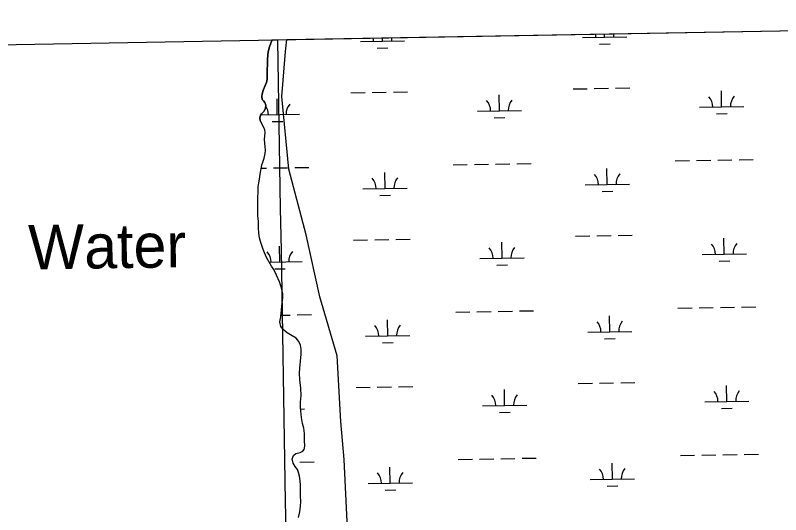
# Model space of a CAD drawing. Extents: x 3903937 to 3942190, y 260677 to 286651.
# Drawn here: x 3912613 to 3914342, y 283217 to 284345 of the extents above; entities that cross this region are included whole.
import ezdxf

# ---------------------------------------------------------------- set-up
doc = ezdxf.new("R2010")
doc.units = 0
for name, color, linetype in [('V-GRID-FRAM', 7, 'Continuous'), ('V-GRID-MAJR', 7, 'Continuous'), ('V-RIVR-IDEN', 7, 'Continuous'), ('V-SITE-VEGE', 7, 'Continuous'), ('V-TOPO-SHOR', 7, 'Continuous'), ('V-WETL-SWMP', 7, 'Continuous')]:
    doc.layers.add(name, color=color, linetype=linetype)

msp = doc.modelspace()

# ---------------------------------------------------------------- linework, layer by layer
at = {"layer": 'V-GRID-FRAM'}
msp.add_lwpolyline([(3907892.224, 284196.099), (3939773.201, 284757.23600000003), (3940101.116, 266577.619), (3908204.273, 266016.203), (3907892.224, 284196.099)], dxfattribs=at)
at = {"layer": 'V-GRID-MAJR'}
msp.add_spline([(3913520.414, 266109.772), (3913415.549, 272167.798), (3913310.651, 278227.748), (3913205.754, 284287.69), (3913205.721, 284289.62200000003)], degree=3, dxfattribs=at)
at = {"layer": 'V-SITE-VEGE'}
for p, q in [((3913226.6025512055, 284289.98938413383), (3914840.3981272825, 284318.39379621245)), ((3913223.1040000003, 284263.156), (3913226.6025512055, 284289.98938413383)), ((3913215.301, 284161.6679999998), (3913223.1040000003, 284263.156)), ((3913230.907, 283997.723), (3913215.301, 284161.6679999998)), ((3913269.921, 283849.395), (3913230.907, 283997.723)), ((3913301.137, 283708.869), (3913269.921, 283849.395)), ((3913340.149, 283576.153), (3913301.137, 283708.869)), ((3913347.952, 283427.822), (3913340.149, 283576.153)), ((3913355.755, 283341.946), (3913347.952, 283427.822)), ((3913363.558, 283185.808), (3913355.755, 283341.946))]:
    msp.add_line(p, q, dxfattribs=at)
at = {"layer": 'V-TOPO-SHOR'}
for points in [[(3913193.2026698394, 284289.40151290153), (3913190.299, 284282.066), (3913187.352, 284273.605), (3913184.211, 284262.196), (3913183.23, 284255.9), (3913182.646, 284244.294), (3913182.847, 284232.099), (3913182.0640000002, 284223.048), (3913181.872, 284213.214), (3913181.878, 284200.428), (3913180.504, 284193.344), (3913176.967, 284186.262), (3913173.626, 284177.016), (3913170.2860000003, 284167.572), (3913169.698, 284161.473), (3913170.882, 284154.787), (3913173.637, 284151.837), (3913176.393, 284147.903), (3913178.558, 284141.61), (3913178.169, 284135.316), (3913175.222, 284128.431), (3913169.322, 284122.721), (3913166.569, 284119.18), (3913165.59, 284112.295), (3913166.379, 284107.574), (3913173.151, 284093.666)], [(3913192.001, 283778.561), (3913180.559, 283798.355), (3913175.81, 283808.81200000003), (3913172.037, 283818.02400000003), (3913169.463, 283825.14), (3913166.5360000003, 283834.26), (3913164.591, 283842.29), (3913163.075, 283853.155), (3913162.426, 283865.162), (3913161.893, 283879.628), (3913160.9450000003, 283892.253), (3913160.558, 283906.254), (3913161.119, 283921.777), (3913161.779, 283957.443), (3913163.163, 283966.881), (3913164.376, 283975.24), (3913165.858, 283985.982), (3913167.231, 283994.647), (3913168.734, 284002.006), (3913170.128, 284007.365), (3913171.691, 284013.569), (3913174.833, 284022.36100000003), (3913177.538, 284032.619), (3913178.275, 284040.14400000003), (3913177.555, 284047.69), (3913176.3030000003, 284055.938), (3913175.824, 284064.173), (3913176.572, 284072.389), (3913177.3740000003, 284079.142), (3913176.275, 284087.158), (3913173.151, 284093.666)], [(3913252.794, 283211.25), (3913255.301, 283223.436), (3913257.203, 283236.4), (3913257.615, 283247.465), (3913257.2630000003, 283258.93), (3913256.7860000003, 283267.39400000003), (3913257.291, 283284.227), (3913256.0670000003, 283293.934), (3913254.623, 283304.492), (3913252.9820000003, 283312.362), (3913250.4020000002, 283319.094), (3913245.134, 283326.176), (3913240.336, 283333.715), (3913238.2630000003, 283343.36100000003), (3913241.004, 283351.004), (3913246.539, 283355.68200000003), (3913256.417, 283357.828), (3913262.383, 283360.652), (3913265.596, 283364.367), (3913266.72, 283371.961), (3913266.3910000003, 283384.806), (3913265.9590000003, 283400.731), (3913264.468, 283412.983), (3913261.637, 283423.331), (3913259.552, 283436.97500000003), (3913257.2260000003, 283459.31200000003), (3913257.1950000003, 283471.539), (3913258.436, 283486.358), (3913257.629, 283502.904), (3913255.407, 283522.163), (3913254.873, 283536.551), (3913255.9050000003, 283547.993), (3913257.16, 283563.658), (3913258.426, 283579.938), (3913258.5300000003, 283591.087), (3913257.363, 283599.717), (3913253.742, 283608.696), (3913247.2460000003, 283615.722), (3913238.265, 283621.481), (3913226.913, 283627.896), (3913217.656, 283635.506), (3913212.61, 283641.969), (3913210.7830000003, 283652.533), (3913212.8170000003, 283664.188), (3913215.944, 283695.50800000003), (3913217.269, 283706.098), (3913217.433, 283716.168), (3913214.4250000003, 283729.675), (3913209.413, 283742.983), (3913202.589, 283758.318), (3913196.72, 283770.871), (3913192.001, 283778.561)]]:
    msp.add_lwpolyline(points, dxfattribs=at)
at = {"layer": 'V-WETL-SWMP'}
for p, q in [((3913193.203086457, 284289.4015202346), (3915021.5893509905, 284321.58294250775)), ((3913190.3000000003, 284282.065), (3913193.203086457, 284289.4015202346)), ((3913392.329723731, 284285.62953828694), (3913492.3142362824, 284287.3894388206)), ((3913442.3219800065, 284286.50948855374), (3913442.1939358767, 284293.78400758)), ((3913894.159990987, 284294.4626198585), (3913994.144503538, 284296.2225203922)), ((3913944.152247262, 284295.34257012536), (3913944.024209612, 284302.61672102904)), ((3913184.21, 284262.195), (3913187.353, 284273.605)), ((3913187.353, 284273.605), (3913190.3000000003, 284282.065)), ((3913430.5954087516, 284270.86969035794), (3913454.591691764, 284271.2920664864)), ((3913932.4256760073, 284279.7027719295), (3913956.4219590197, 284280.12514805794)), ((3913182.645, 284244.294), (3913183.23, 284255.9)), ((3913183.23, 284255.9), (3913184.21, 284262.195)), ((3913182.847, 284232.09799999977), (3913182.645, 284244.294)), ((3913181.872, 284213.21399999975), (3913182.0640000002, 284223.049)), ((3913182.0640000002, 284223.049), (3913182.847, 284232.09799999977)), ((3913181.877, 284200.4279999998), (3913181.872, 284213.21399999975)), ((3913173.626, 284177.016), (3913176.966, 284186.262)), ((3913176.966, 284186.262), (3913180.503, 284193.34499999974)), ((3913180.503, 284193.34499999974), (3913181.877, 284200.4279999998)), ((3913169.699, 284161.474), (3913170.2860000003, 284167.572)), ((3913170.2860000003, 284167.572), (3913173.626, 284177.016)), ((3913370.956837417, 284169.8034582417), (3913402.9518814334, 284170.3666264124)), ((3913418.9494034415, 284170.6482104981), (3913450.9444474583, 284171.2113786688)), ((3913466.9419694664, 284171.4929627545), (3913498.9370134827, 284172.05613092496)), ((3913872.787104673, 284178.6365398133), (3913904.7821486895, 284179.199707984)), ((3913920.779670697, 284179.48129206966), (3913952.774714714, 284180.04446024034)), ((3913968.772236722, 284180.32604432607), (3914000.7672807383, 284180.8892124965)), ((3914208.396367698, 284138.1066519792), (3914207.762803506, 284174.1010764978)), ((3913170.882, 284154.786), (3913169.699, 284161.474)), ((3913173.637, 284151.837), (3913170.882, 284154.786)), ((3913176.393, 284147.904), (3913173.637, 284151.837)), ((3913204.735833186, 284120.4404888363), (3913204.1022689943, 284156.43491335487)), ((3913706.566100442, 284129.2735704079), (3913705.93253625, 284165.2679949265)), ((3913175.221, 284128.42999999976), (3913178.169, 284135.316)), ((3913178.559, 284141.61), (3913176.393, 284147.904)), ((3913178.169, 284135.316), (3913178.559, 284141.61)), ((3914158.4041114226, 284137.2267017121), (3914258.388623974, 284138.98660224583)), ((3913165.59, 284112.295), (3913166.5700000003, 284119.18)), ((3913166.5700000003, 284119.18), (3913169.322, 284122.722)), ((3913167.0337428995, 284119.7768667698), (3913254.7280894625, 284121.3204391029)), ((3913169.322, 284122.722), (3913175.221, 284128.42999999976)), ((3913656.573844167, 284128.3936201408), (3913756.558356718, 284130.15352067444)), ((3914196.669796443, 284122.46685378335), (3914220.6660794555, 284122.88922991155)), ((3913166.378, 284107.575), (3913165.59, 284112.295)), ((3913173.1520000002, 284093.6669999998), (3913166.378, 284107.575)), ((3913193.0092619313, 284104.80069064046), (3913217.0055449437, 284105.22306676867)), ((3913694.8395291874, 284113.633772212), (3913718.8358122, 284114.0561483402)), ((3913176.275, 284087.1569999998), (3913173.1520000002, 284093.6669999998)), ((3913177.375, 284079.14199999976), (3913176.275, 284087.1569999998)), ((3913175.823, 284064.1729999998), (3913176.572, 284072.389)), ((3913176.304, 284055.9379999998), (3913175.823, 284064.1729999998)), ((3913176.572, 284072.389), (3913177.375, 284079.14199999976)), ((3913177.554, 284047.68999999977), (3913176.304, 284055.9379999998)), ((3913178.276, 284040.14299999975), (3913177.554, 284047.68999999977)), ((3913174.833, 284022.35999999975), (3913177.538, 284032.619)), ((3913177.538, 284032.619), (3913178.276, 284040.14299999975)), ((3913170.129, 284007.365), (3913171.691, 284013.568)), ((3913171.691, 284013.568), (3913174.833, 284022.35999999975)), ((3914103.6820452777, 284016.1738997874), (3914135.677089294, 284016.7370679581)), ((3914151.6746113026, 284017.01865204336), (3914183.669655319, 284017.5818202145)), ((3914199.6671773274, 284017.8634042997), (3914231.6622213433, 284018.4265724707)), ((3914247.6597433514, 284018.7081565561), (3914279.6547873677, 284019.2713247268)), ((3913165.859, 283985.982), (3913167.23, 283994.648)), ((3913167.23, 283994.648), (3913168.734, 284002.006)), ((3913168.264471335, 283999.7089309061), (3913180.009120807, 283999.9156570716)), ((3913168.734, 284002.006), (3913170.129, 284007.365)), ((3913196.0066428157, 284000.1972411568), (3913228.0016868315, 284000.76040932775)), ((3913243.99920884, 284001.04199341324), (3913275.9942528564, 284001.6051615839)), ((3913601.851778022, 284007.3408182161), (3913633.8468220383, 284007.9039863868)), ((3913649.844344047, 284008.18557047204), (3913681.839388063, 284008.7487386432)), ((3913697.8369100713, 284009.0303227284), (3913729.831954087, 284009.5934908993)), ((3913745.8294760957, 284009.8750749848), (3913777.824520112, 284010.4382431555)), ((3913950.0069963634, 283962.7190929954), (3913949.373432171, 283998.71351751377)), ((3913164.376, 283975.24099999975), (3913165.859, 283985.982)), ((3913448.1767291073, 283953.88601142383), (3913447.543164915, 283989.8804359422)), ((3913161.779, 283957.4439999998), (3913163.163, 283966.8799999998)), ((3913163.163, 283966.8799999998), (3913164.376, 283975.24099999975)), ((3913900.0147400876, 283961.8391427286), (3913999.999252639, 283963.59904326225)), ((3913161.12, 283921.77699999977), (3913161.779, 283957.4439999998)), ((3913398.184472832, 283953.006061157), (3913498.168985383, 283954.7659616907)), ((3913938.2804251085, 283947.0792947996), (3913962.2767081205, 283947.50167092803)), ((3913436.450157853, 283938.246213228), (3913460.446440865, 283938.6685893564)), ((3913160.559, 283906.254), (3913161.12, 283921.77699999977)), ((3913160.946, 283892.2529999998), (3913160.559, 283906.254)), ((3913161.893, 283879.62699999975), (3913160.946, 283892.2529999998)), ((3913162.426, 283865.1619999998), (3913161.893, 283879.62699999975)), ((3913163.076, 283853.156), (3913162.426, 283865.1619999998)), ((3913164.591, 283842.29), (3913163.076, 283853.156)), ((3913166.5360000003, 283834.261), (3913164.591, 283842.29)), ((3913376.8115865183, 283837.1799811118), (3913408.8066305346, 283837.74314928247)), ((3913424.8041525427, 283838.0247333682), (3913456.799196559, 283838.5879015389)), ((3913472.796718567, 283838.86948562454), (3913504.791762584, 283839.432653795)), ((3913878.641853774, 283846.01306268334), (3913910.6368977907, 283846.576230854)), ((3913926.6344197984, 283846.85781493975), (3913958.6294638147, 283847.42098311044)), ((3913974.626985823, 283847.70256719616), (3914006.6220298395, 283848.2657353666)), ((3914214.251116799, 283805.4831748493), (3914213.617552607, 283841.47759936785)), ((3913169.463, 283825.1399999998), (3913166.5360000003, 283834.261)), ((3913172.038, 283818.02399999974), (3913169.463, 283825.1399999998)), ((3913210.5905822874, 283787.81701170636), (3913209.957018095, 283823.81143622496)), ((3913712.420849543, 283796.6500932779), (3913711.7872853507, 283832.6445177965)), ((3913175.809, 283808.81200000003), (3913172.038, 283818.02399999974)), ((3913180.559, 283798.354), (3913175.809, 283808.81200000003)), ((3914164.2588605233, 283804.6032245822), (3914264.2433730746, 283806.36312511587)), ((3913192.001, 283778.56), (3913180.559, 283798.354)), ((3913186.8910842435, 283787.39985950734), (3913260.5828385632, 283788.696961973)), ((3913662.4285932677, 283795.7701430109), (3913762.413105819, 283797.53004354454)), ((3914202.5245455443, 283789.84337665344), (3914226.5208285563, 283790.26575278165)), ((3913196.72, 283770.86999999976), (3913192.001, 283778.56)), ((3913202.59, 283758.3179999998), (3913196.72, 283770.86999999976)), ((3913198.8640110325, 283772.1772135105), (3913222.8602940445, 283772.5995896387)), ((3913700.6942782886, 283781.0102950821), (3913724.6905613, 283781.4326712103)), ((3913209.414, 283742.982), (3913202.59, 283758.3179999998)), ((3913214.4250000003, 283729.67399999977), (3913209.414, 283742.982)), ((3913217.434, 283716.16899999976), (3913214.4250000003, 283729.67399999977)), ((3913215.944, 283695.509), (3913217.27, 283706.099)), ((3913217.27, 283706.099), (3913217.434, 283716.16899999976)), ((3913212.818, 283664.188), (3913215.944, 283695.509)), ((3914109.5367943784, 283683.5504226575), (3914141.531838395, 283684.1135908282)), ((3914157.5293604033, 283684.3951749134), (3914189.52440442, 283684.95834308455)), ((3914205.5219264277, 283685.2399271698), (3914237.5169704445, 283685.8030953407)), ((3914253.5144924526, 283686.0846794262), (3914285.5095364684, 283686.6478475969)), ((3913213.1757935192, 283667.7729170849), (3913233.8564359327, 283668.13693219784)), ((3913249.8539579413, 283668.4185162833), (3913281.849001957, 283668.98168445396)), ((3913607.7065271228, 283674.7173410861), (3913639.7015711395, 283675.2805092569)), ((3913655.699093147, 283675.5620933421), (3913687.6941371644, 283676.1252615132)), ((3913703.691659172, 283676.4068455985), (3913735.6867031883, 283676.9700137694)), ((3913751.684225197, 283677.25159785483), (3913783.6792692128, 283677.8147660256)), ((3913955.8617454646, 283630.0956158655), (3913955.2281812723, 283666.0900403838)), ((3913210.7830000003, 283652.533), (3913212.818, 283664.188)), ((3913212.61, 283641.969), (3913210.7830000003, 283652.533)), ((3913454.0314782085, 283621.26253429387), (3913453.397914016, 283657.25695881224)), ((3913217.656, 283635.5049999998), (3913212.61, 283641.969)), ((3913226.913, 283627.8949999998), (3913217.656, 283635.5049999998)), ((3913905.869489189, 283629.21566559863), (3914005.85400174, 283630.9755661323)), ((3913238.265, 283621.481), (3913226.913, 283627.8949999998)), ((3913247.245, 283615.722), (3913238.265, 283621.481)), ((3913253.7430000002, 283608.695), (3913247.245, 283615.722)), ((3913404.039221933, 283620.3825840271), (3913504.0237344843, 283622.1424845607)), ((3913944.1351742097, 283614.45581766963), (3913968.1314572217, 283614.87819379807)), ((3913257.364, 283599.7169999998), (3913253.7430000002, 283608.695)), ((3913258.5300000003, 283591.086), (3913257.364, 283599.7169999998)), ((3913442.304906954, 283605.62273609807), (3913466.301189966, 283606.0451122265)), ((3913257.16, 283563.657), (3913258.4250000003, 283579.9379999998)), ((3913258.4250000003, 283579.9379999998), (3913258.5300000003, 283591.086)), ((3913255.9050000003, 283547.992), (3913257.16, 283563.657)), ((3913254.872, 283536.551), (3913255.9050000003, 283547.992)), ((3913255.407, 283522.16399999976), (3913254.872, 283536.551)), ((3913257.63, 283502.904), (3913255.407, 283522.16399999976)), ((3913884.4966028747, 283513.38958555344), (3913916.4916468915, 283513.9527537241)), ((3913932.4891688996, 283514.2343378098), (3913964.484212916, 283514.7975059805)), ((3913980.4817349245, 283515.0790900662), (3914012.4767789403, 283515.64225823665)), ((3913258.436, 283486.35899999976), (3913257.63, 283502.904)), ((3913382.666335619, 283504.5565039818), (3913414.661379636, 283505.1196721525)), ((3913430.658901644, 283505.4012562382), (3913462.65394566, 283505.9644244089)), ((3913478.651467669, 283506.24600849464), (3913510.6465116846, 283506.8091766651)), ((3913718.2755986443, 283464.026616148), (3913717.642034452, 283500.02104066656)), ((3914220.1058659, 283472.85969771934), (3914219.4723017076, 283508.85412223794)), ((3913257.1950000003, 283471.539), (3913258.436, 283486.35899999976)), ((3913257.2260000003, 283459.31199999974), (3913257.1950000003, 283471.539)), ((3913259.5530000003, 283436.97500000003), (3913257.2260000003, 283459.31199999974)), ((3913668.2833423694, 283463.1466658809), (3913768.26785492, 283464.9065664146)), ((3914170.113609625, 283471.97974745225), (3914270.098122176, 283473.73964798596)), ((3914208.3792946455, 283457.2198995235), (3914232.3755776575, 283457.6422756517)), ((3913257.5796213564, 283455.91756929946), (3913266.437587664, 283456.073484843)), ((3913706.5490273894, 283448.38681795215), (3913730.5453104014, 283448.80919408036)), ((3913261.637, 283423.331), (3913259.5530000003, 283436.97500000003)), ((3913264.467, 283412.9819999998), (3913261.637, 283423.331)), ((3913265.9590000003, 283400.7309999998), (3913264.467, 283412.9819999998)), ((3913266.3910000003, 283384.80699999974), (3913265.9590000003, 283400.7309999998)), ((3913265.596, 283364.367), (3913266.72, 283371.961)), ((3913266.72, 283371.961), (3913266.3910000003, 283384.80699999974)), ((3913241.003, 283351.004), (3913246.539, 283355.681)), ((3913246.539, 283355.681), (3913256.416, 283357.827)), ((3913256.416, 283357.827), (3913262.383, 283360.652)), ((3913262.383, 283360.65199999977), (3913265.596, 283364.367)), ((3914259.3692415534, 283353.46120229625), (3914291.36428557, 283354.02437046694)), ((3913238.264, 283343.36), (3913241.003, 283351.004)), ((3913240.336, 283333.714), (3913238.264, 283343.36)), ((3913613.5612762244, 283342.0938639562), (3913645.5563202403, 283342.6570321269)), ((3913661.553842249, 283342.9386162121), (3913693.5488862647, 283343.5017843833)), ((3913709.5464082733, 283343.7833684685), (3913741.5414522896, 283344.34653663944)), ((3913757.5389742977, 283344.6281207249), (3913789.5340183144, 283345.1912888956)), ((3914115.39154348, 283350.92694552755), (3914147.386587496, 283351.49011369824)), ((3914163.384109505, 283351.7716977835), (3914195.379153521, 283352.33486595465)), ((3914211.376675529, 283352.61645003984), (3914243.371719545, 283353.1796182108)), ((3913245.1350000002, 283326.1769999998), (3913240.336, 283333.714)), ((3913250.4020000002, 283319.094), (3913245.1350000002, 283326.1769999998)), ((3913252.983, 283312.3619999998), (3913250.4020000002, 283319.094)), ((3913255.708707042, 283335.79503915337), (3913287.703751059, 283336.35820732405)), ((3913459.8862273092, 283288.63905716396), (3913459.2526631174, 283324.6334816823)), ((3913961.716494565, 283297.4721387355), (3913961.0829303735, 283333.4665632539)), ((3913254.623, 283304.492), (3913252.983, 283312.3619999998)), ((3913256.066, 283293.935), (3913254.623, 283304.492)), ((3913257.291, 283284.2259999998), (3913256.066, 283293.935)), ((3913409.8939710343, 283287.7591068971), (3913509.8784835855, 283289.5190074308)), ((3913911.72423829, 283296.5921884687), (3914011.708750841, 283298.3520890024)), ((3913256.7860000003, 283267.3949999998), (3913257.291, 283284.2259999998)), ((3913257.2630000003, 283258.92899999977), (3913256.7860000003, 283267.3949999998)), ((3913448.159656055, 283272.9992589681), (3913472.155939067, 283273.42163509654)), ((3913949.9899233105, 283281.8323405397), (3913973.986206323, 283282.25471666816)), ((3913257.614, 283247.4659999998), (3913257.2630000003, 283258.92899999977)), ((3913255.3000000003, 283223.43599999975), (3913257.203, 283236.4)), ((3913257.203, 283236.4), (3913257.614, 283247.4659999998)), ((3913252.794, 283211.251), (3913255.3000000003, 283223.43599999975))]:
    msp.add_line(p, q, dxfattribs=at)
for centre, radius, start, end in [((3913387.0792435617, 284286.01199747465), 35.24628790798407, 0.2365807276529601, 12.133537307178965), ((3913497.548004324, 284287.9564389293), 35.24628790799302, 169.88331448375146, 181.78023605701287), ((3913888.9095108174, 284294.84507904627), 35.24628790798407, 0.2365807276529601, 12.132927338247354), ((3913999.3782715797, 284296.7895205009), 35.24628790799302, 169.88392445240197, 181.78023605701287), ((3913651.323363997, 284128.77607932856), 35.24628790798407, 0.23658072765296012, 41.78023906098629), ((3913761.7921247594, 284130.72052078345), 35.24628790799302, 140.23657772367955, 181.78023605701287), ((3914153.1536312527, 284137.6091608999), 35.24628790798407, 0.23658072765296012, 41.78023906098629), ((3914263.622392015, 284139.5536023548), 35.24628790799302, 140.23657772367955, 181.78023605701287), ((3913149.4930967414, 284119.94299775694), 35.24628790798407, 0.2365807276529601, 34.72853080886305), ((3913259.9618575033, 284121.88743921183), 35.24628790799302, 140.23657772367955, 181.78023605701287), ((3913392.9339926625, 283953.38852034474), 35.24628790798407, 0.23658072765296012, 41.78023906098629), ((3913503.402753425, 283955.3329617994), 35.24628790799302, 140.23657772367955, 181.78023605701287), ((3913894.764259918, 283962.2216019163), 35.24628790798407, 0.23658072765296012, 41.78023906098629), ((3914005.2330206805, 283964.16604337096), 35.24628790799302, 140.23657772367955, 181.78023605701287), ((3913767.6468738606, 283798.0970436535), 35.24628790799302, 140.23657772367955, 181.78023605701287), ((3914159.008380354, 283804.9856837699), 35.24628790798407, 0.23658072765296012, 41.78023906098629), ((3914269.4771411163, 283806.9301252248), 35.24628790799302, 140.23657772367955, 181.78023605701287), ((3913155.3478458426, 283787.31952062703), 35.24628790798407, 0.23658072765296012, 41.78023906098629), ((3913265.8166066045, 283789.2639620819), 35.24628790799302, 140.23657772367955, 181.78023605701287), ((3913657.1781130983, 283796.1526021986), 35.24628790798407, 0.23658072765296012, 41.78023906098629), ((3913900.6190090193, 283629.5981247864), 35.24628790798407, 0.23658072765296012, 41.78023906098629), ((3914011.0877697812, 283631.54256624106), 35.24628790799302, 140.23657772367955, 181.78023605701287), ((3913398.7887417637, 283620.7650432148), 35.24628790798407, 0.23658072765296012, 41.78023906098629), ((3913509.2575025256, 283622.70948466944), 35.24628790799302, 140.23657772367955, 181.78023605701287), ((3914164.8631294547, 283472.36220664), 35.24628790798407, 0.23658072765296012, 41.78023906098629), ((3914275.331890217, 283474.3066480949), 35.24628790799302, 140.23657772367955, 181.78023605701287), ((3913663.032862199, 283463.5291250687), 35.24628790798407, 0.23658072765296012, 41.78023906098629), ((3913773.501622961, 283465.4735665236), 35.24628790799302, 140.23657772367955, 181.78023605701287), ((3913906.4737581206, 283296.97464765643), 35.24628790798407, 0.23658072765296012, 41.78023906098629), ((3914016.942518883, 283298.9190891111), 35.24628790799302, 140.23657772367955, 181.78023605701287), ((3913404.643490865, 283288.1415660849), 35.24628790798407, 0.23658072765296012, 41.78023906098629), ((3913515.1122516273, 283290.08600753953), 35.24628790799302, 140.23657772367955, 181.78023605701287)]:
    msp.add_arc(centre, radius, start, end, dxfattribs=at)

# ---------------------------------------------------------------- texts
at = {"layer": 'V-RIVR-IDEN'}
msp.add_text('Water', height=99.99980199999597, rotation=0.8107055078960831, dxfattribs=at).set_placement((3912642.880674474, 283771.0664326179))

doc.saveas('drawing.dxf')
